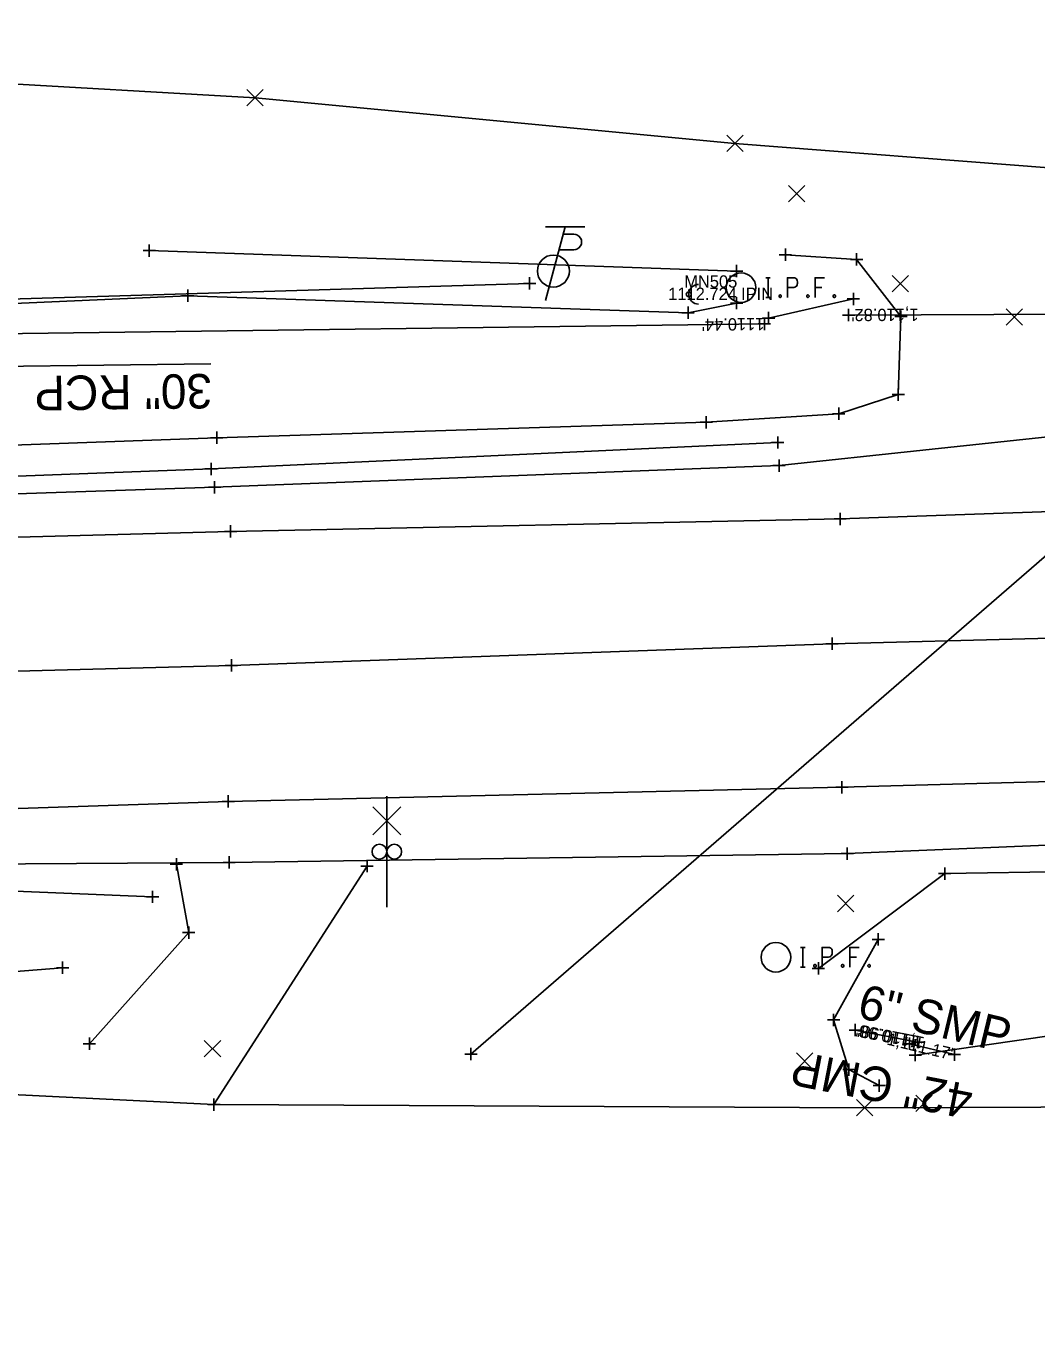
# Model space of a CAD drawing. Extents: x 2402028 to 2407435, y 498611 to 499105.
# Drawn here: x 2402973.4 to 2403055.5, y 498611.7 to 498717.9 of the extents above; entities that cross this region are included whole.
import ezdxf

# ---------------------------------------------------------------- set-up
doc = ezdxf.new("R2010")
doc.units = 0
for name, color, linetype in [('_CIVIL_CONSTRUCTION', 7, 'Continuous'), ('Default', 7, 'Continuous'), ('DR_X_Ditch', 7, 'Continuous'), ('DR_X_Storm_Sewer', 7, 'Continuous'), ('DR_X_Text', 7, 'Continuous'), ('PV_X_COP', 7, 'Continuous'), ('PV_X_Driveway', 7, 'Continuous'), ('PV_X_EOP', 7, 'Continuous'), ('PV_X_Shoulder', 7, 'Continuous'), ('RD_X_GR_Lt', 7, 'Continuous'), ('RD_X_RR_1', 7, 'Continuous'), ('RW_X_CL_100_Bearings', 7, 'Continuous'), ('RW_X_CL_100_Cardinal_Points', 7, 'Continuous'), ('RW_X_CL_100_Stations', 7, 'Continuous'), ('RW_X_CL_500_Bearings', 7, 'Continuous'), ('RW_X_CL_500_Cardinal_Points', 7, 'Continuous'), ('RW_X_CL_500_Distances', 7, 'Continuous'), ('RW_X_CL_500_Stations', 7, 'Continuous'), ('RW_X_Esmt_RR', 7, 'Continuous'), ('SC_Scratch1', 7, 'Continuous'), ('SV_X_Break_Lines', 7, 'Continuous'), ('SV_X_Terrain_Boundary', 7, 'Continuous'), ('UT_X_Telecom', 7, 'Continuous')]:
    doc.layers.add(name, color=color, linetype=linetype)

msp = doc.modelspace()

# ---------------------------------------------------------------- linework, layer by layer
at = {"layer": 'Default'}
for p, q in [((2403045.13, 498635.18), (2403045.13, 498635.18)), ((2403045.78, 498635.32), (2403045.78, 498635.32))]:
    msp.add_line(p, q, dxfattribs=at)
at = {"layer": 'DR_X_Ditch'}
msp.add_lwpolyline([(2403033.68, 498694.14), (2403040.56, 498695.7)], dxfattribs=at)
at = {"layer": 'DR_X_Storm_Sewer'}
for p, q in [((2403115.62, 498694.73), (2403040.17, 498694.38)), ((2403033.33, 498693.66), (2402928.26, 498692.31)), ((2403045.78, 498635.32), (2403040.71, 498636.3)), ((2403045.13, 498635.18), (2403048.77, 498634.3))]:
    msp.add_line(p, q, dxfattribs=at)
at = {"layer": 'DR_X_Text'}
msp.add_line((2402969.29, 498690.19), (2402988.37, 498690.43), dxfattribs=at)
at = {"layer": 'PV_X_COP'}
msp.add_lwpolyline([(2402290.78, 498650.6), (2402340.95, 498651.54), (2402390.57, 498652.34), (2402439.7, 498652.49), (2402489.93, 498654.64), (2402539.81, 498655.53), (2402589.95, 498657.15), (2402640.38, 498659.77), (2402689.17, 498658.83), (2402739.11, 498659.65), (2402789.43, 498660.95), (2402839.82, 498661.75), (2402889.36, 498663.57), (2402939.81, 498664.58), (2402990.03, 498665.92), (2403038.83, 498667.68), (2403088.96, 498668.97), (2403139.3, 498669.99), (2403188.98, 498670.93), (2403236.78, 498672.43), (2403288.95, 498673.92), (2403339.4, 498675.07), (2403388.6, 498676.54)], dxfattribs=at)
at = {"layer": 'PV_X_Driveway'}
for points in [[(2402978.5, 498635.18), (2402986.56, 498644.22), (2402985.56, 498649.77)], [(2403001.06, 498649.62), (2402988.61, 498630.24)]]:
    msp.add_lwpolyline(points, dxfattribs=at)
at = {"layer": 'PV_X_EOP'}
for points in [[(2402289.63, 498661.52), (2402339.86, 498662.34), (2402390.35, 498663.57), (2402439.38, 498664.47), (2402489.03, 498665.67), (2402538.63, 498666.7), (2402622.2, 498668.45), (2402639.44, 498668.97), (2402688.21, 498669.91), (2402738.3, 498670.77), (2402784.26, 498671.54), (2402839.07, 498673.4), (2402887.81, 498674.54), (2402939.07, 498675.44), (2402989.96, 498676.81), (2403039.49, 498677.82), (2403088.59, 498679.54), (2403138.58, 498681), (2403188.48, 498682.36), (2403236.31, 498683.8), (2403287.8, 498685.14), (2403338.61, 498686.54), (2403387.34, 498688.53)], [(2402290.91, 498639.29), (2402341.07, 498640.3), (2402390.61, 498641.23), (2402440.65, 498642.38), (2402490.15, 498643.23), (2402540.35, 498644.45), (2402590.8, 498645.77), (2402640.33, 498646.73), (2402690.18, 498647.64), (2402739.92, 498648.63), (2402790, 498649.56), (2402840.05, 498650.65), (2402889.89, 498651.78), (2402940.17, 498653.2), (2402989.78, 498654.87), (2403039.63, 498656.02), (2403089.54, 498657.39), (2403140.04, 498658.56), (2403189.82, 498659.81), (2403238.57, 498661.04), (2403289.76, 498662.62), (2403340.13, 498663.91), (2403389.07, 498665.43)]]:
    msp.add_lwpolyline(points, dxfattribs=at)
at = {"layer": 'PV_X_Shoulder'}
for p, q in [((2403034.53, 498682.16), (2403062.85, 498685.18)), ((2402988.67, 498680.4), (2403034.53, 498682.16)), ((2402938.19, 498678.69), (2402988.67, 498680.4))]:
    msp.add_line(p, q, dxfattribs=at)
msp.add_lwpolyline([(2402291.13, 498635.58), (2402341.06, 498636.96), (2402390.62, 498637.69), (2402440.73, 498638.55), (2402490.3, 498639.85), (2402540.78, 498641.01), (2402590.73, 498641.96), (2402640.23, 498642.72), (2402690.38, 498643.95), (2402740.06, 498644.93), (2402790, 498645.7), (2402840.23, 498646.8), (2402889.99, 498648.42), (2402940.22, 498649.59), (2402989.85, 498649.92), (2403040.06, 498650.63), (2403089.93, 498652.73), (2403140.24, 498654.26), (2403189.57, 498655.62), (2403238.67, 498657.76), (2403289.89, 498659.04), (2403340.12, 498659.5), (2403389.1, 498660.69)], dxfattribs=at)
at = {"layer": 'RD_X_GR_Lt'}
for points in [[(2402671.34, 498674.03), (2402687.6, 498674.22), (2402737.25, 498674.66), (2402787.14, 498675.21), (2402837.72, 498677.2), (2402886.73, 498678.51), (2402937.55, 498679.97), (2402988.38, 498681.88), (2403034.42, 498684.03)], [(2402983.63, 498647.12), (2402940.38, 498648.9), (2402890.36, 498647.43), (2402840.29, 498646.11), (2402790.18, 498644.6), (2402758.45, 498643.74)]]:
    msp.add_lwpolyline(points, dxfattribs=at)
at = {"layer": 'RD_X_RR_1'}
msp.add_lwpolyline([(2403009.49, 498634.34), (2403091.64, 498705.57)], dxfattribs=at)
at = {"layer": 'RW_X_CL_100_Stations'}
for points in [[(2403033.46, 498697.41), (2403033.81, 498697.41)], [(2403033.63, 498695.81), (2403033.63, 498697.41)], [(2403035.2, 498695.81), (2403035.2, 498697.41), (2403035.73, 498697.41), (2403035.78, 498697.4), (2403035.86, 498697.37), (2403035.89, 498697.35), (2403035.93, 498697.32), (2403035.97, 498697.26), (2403036, 498697.2), (2403036.03, 498697.09), (2403036.03, 498696.94), (2403036.01, 498696.89), (2403035.99, 498696.82), (2403035.95, 498696.73), (2403035.9, 498696.69), (2403035.87, 498696.67), (2403035.82, 498696.64), (2403035.73, 498696.63), (2403035.2, 498696.63)], [(2403038.21, 498697.41), (2403037.45, 498697.41), (2403037.45, 498695.81)], [(2403037.45, 498696.63), (2403037.99, 498696.63)], [(2403033.46, 498695.81), (2403033.81, 498695.81)], [(2403034.59, 498696.02), (2403034.65, 498696.02), (2403034.68, 498696), (2403034.71, 498695.95), (2403034.71, 498695.89), (2403034.68, 498695.83), (2403034.65, 498695.81), (2403034.59, 498695.81), (2403034.56, 498695.83), (2403034.53, 498695.89), (2403034.53, 498695.95), (2403034.56, 498696), (2403034.59, 498696.02)], [(2403036.84, 498696.02), (2403036.9, 498696.02), (2403036.93, 498696), (2403036.96, 498695.95), (2403036.96, 498695.89), (2403036.93, 498695.83), (2403036.9, 498695.81), (2403036.84, 498695.81), (2403036.81, 498695.83), (2403036.77, 498695.89), (2403036.77, 498695.95), (2403036.81, 498696), (2403036.84, 498696.02)], [(2403038.99, 498696.02), (2403039.05, 498696.02), (2403039.08, 498696), (2403039.11, 498695.95), (2403039.11, 498695.89), (2403039.08, 498695.83), (2403039.05, 498695.81), (2403038.99, 498695.81), (2403038.96, 498695.83), (2403038.92, 498695.89), (2403038.92, 498695.95), (2403038.96, 498696), (2403038.99, 498696.02)], [(2403036.28, 498643.01), (2403036.64, 498643.01)], [(2403036.46, 498641.41), (2403036.46, 498643.01)], [(2403038.02, 498641.41), (2403038.02, 498643.01), (2403038.55, 498643.01), (2403038.61, 498643), (2403038.69, 498642.97), (2403038.72, 498642.95), (2403038.75, 498642.92), (2403038.8, 498642.86), (2403038.83, 498642.8), (2403038.85, 498642.7), (2403038.85, 498642.55), (2403038.84, 498642.5), (2403038.82, 498642.42), (2403038.77, 498642.33), (2403038.73, 498642.29), (2403038.7, 498642.27), (2403038.64, 498642.24), (2403038.55, 498642.23), (2403038.02, 498642.23)], [(2403041.03, 498643.01), (2403040.27, 498643.01), (2403040.27, 498641.41)], [(2403040.27, 498642.23), (2403040.81, 498642.23)], [(2403036.28, 498641.41), (2403036.64, 498641.41)], [(2403037.42, 498641.63), (2403037.47, 498641.63), (2403037.51, 498641.6), (2403037.54, 498641.55), (2403037.54, 498641.49), (2403037.51, 498641.44), (2403037.47, 498641.41), (2403037.42, 498641.41), (2403037.38, 498641.44), (2403037.35, 498641.49), (2403037.35, 498641.55), (2403037.38, 498641.6), (2403037.42, 498641.63)], [(2403039.67, 498641.63), (2403039.72, 498641.63), (2403039.75, 498641.6), (2403039.79, 498641.55), (2403039.79, 498641.49), (2403039.75, 498641.44), (2403039.72, 498641.41), (2403039.67, 498641.41), (2403039.63, 498641.44), (2403039.6, 498641.49), (2403039.6, 498641.55), (2403039.63, 498641.6), (2403039.67, 498641.63)], [(2403041.82, 498641.63), (2403041.87, 498641.63), (2403041.9, 498641.6), (2403041.94, 498641.55), (2403041.94, 498641.49), (2403041.9, 498641.44), (2403041.87, 498641.41), (2403041.82, 498641.41), (2403041.78, 498641.44), (2403041.75, 498641.49), (2403041.75, 498641.55), (2403041.78, 498641.6), (2403041.82, 498641.63)]]:
    msp.add_lwpolyline(points, dxfattribs=at)
for centre in [(2403031.44, 498696.61), (2403034.27, 498642.21)]:
    msp.add_circle(centre, 1.2, dxfattribs=at)
at = {"layer": 'RW_X_CL_500_Bearings'}
for p, q in [((2402982.86, 498699.62), (2402983.86, 498699.62)), ((2402983.36, 498700.12), (2402983.36, 498699.12)), ((2402983.36, 498699.62), (2402983.36, 498699.62)), ((2403035.04, 498699.78), (2403035.04, 498698.78)), ((2403031.07, 498698.45), (2403031.07, 498697.45)), ((2403034.54, 498699.28), (2403035.54, 498699.28)), ((2403035.04, 498699.28), (2403035.04, 498699.28)), ((2403040.33, 498698.9), (2403041.33, 498698.9)), ((2403040.83, 498699.4), (2403040.83, 498698.4)), ((2403040.83, 498698.9), (2403040.83, 498698.9)), ((2403014.26, 498697.45), (2403014.26, 498696.45)), ((2403030.57, 498697.95), (2403031.57, 498697.95)), ((2403031.07, 498697.95), (2403031.07, 498697.95)), ((2402986.48, 498696.45), (2402986.48, 498695.45)), ((2403013.76, 498696.95), (2403014.76, 498696.95)), ((2403014.26, 498696.95), (2403014.26, 498696.95)), ((2402985.98, 498695.95), (2402986.98, 498695.95)), ((2402986.48, 498695.95), (2402986.48, 498695.95)), ((2403030.57, 498695.35), (2403031.57, 498695.35)), ((2403031.07, 498695.85), (2403031.07, 498694.85)), ((2403031.07, 498695.35), (2403031.07, 498695.35)), ((2403040.06, 498695.7), (2403041.06, 498695.7)), ((2403040.56, 498696.2), (2403040.56, 498695.2)), ((2403040.56, 498695.7), (2403040.56, 498695.7)), ((2403026.63, 498694.57), (2403027.63, 498694.57)), ((2403027.13, 498695.07), (2403027.13, 498694.07)), ((2403027.13, 498694.57), (2403027.13, 498694.57)), ((2403033.68, 498694.64), (2403033.68, 498693.64)), ((2403043.92, 498694.26), (2403044.92, 498694.26)), ((2403044.42, 498694.76), (2403044.42, 498693.76)), ((2403044.42, 498694.26), (2403044.42, 498694.26)), ((2403033.18, 498694.14), (2403034.18, 498694.14)), ((2403033.68, 498694.14), (2403033.68, 498694.14)), ((2403043.71, 498687.92), (2403044.71, 498687.92)), ((2403044.21, 498688.42), (2403044.21, 498687.42)), ((2403044.21, 498687.92), (2403044.21, 498687.92)), ((2403039.38, 498686.87), (2403039.38, 498685.87)), ((2403028.61, 498686.17), (2403028.61, 498685.17)), ((2403038.88, 498686.37), (2403039.88, 498686.37)), ((2403039.38, 498686.37), (2403039.38, 498686.37)), ((2402988.84, 498684.91), (2402988.84, 498683.91)), ((2403028.11, 498685.67), (2403029.11, 498685.67)), ((2403028.61, 498685.67), (2403028.61, 498685.67)), ((2402988.34, 498684.41), (2402989.34, 498684.41)), ((2402988.84, 498684.41), (2402988.84, 498684.41)), ((2403033.92, 498684.03), (2403034.92, 498684.03)), ((2403034.42, 498684.53), (2403034.42, 498683.53)), ((2403034.42, 498684.03), (2403034.42, 498684.03)), ((2403034.53, 498682.66), (2403034.53, 498681.66)), ((2402987.88, 498681.88), (2402988.88, 498681.88)), ((2402988.38, 498682.38), (2402988.38, 498681.38)), ((2402988.38, 498681.88), (2402988.38, 498681.88)), ((2403034.03, 498682.16), (2403035.03, 498682.16)), ((2403034.53, 498682.16), (2403034.53, 498682.16)), ((2402988.17, 498680.4), (2402989.17, 498680.4)), ((2402988.67, 498680.9), (2402988.67, 498679.9)), ((2402988.67, 498680.4), (2402988.67, 498680.4)), ((2403039.49, 498678.32), (2403039.49, 498677.32)), ((2402989.96, 498677.31), (2402989.96, 498676.31)), ((2403038.99, 498677.82), (2403039.99, 498677.82)), ((2403039.49, 498677.82), (2403039.49, 498677.82)), ((2402989.46, 498676.81), (2402990.46, 498676.81)), ((2402989.96, 498676.81), (2402989.96, 498676.81)), ((2403038.33, 498667.68), (2403039.33, 498667.68)), ((2403038.83, 498668.18), (2403038.83, 498667.18)), ((2403038.83, 498667.68), (2403038.83, 498667.68)), ((2402989.53, 498665.92), (2402990.53, 498665.92)), ((2402990.03, 498666.42), (2402990.03, 498665.42)), ((2402990.03, 498665.92), (2402990.03, 498665.92)), ((2403039.13, 498656.02), (2403040.13, 498656.02)), ((2403039.63, 498656.52), (2403039.63, 498655.52)), ((2403039.63, 498656.02), (2403039.63, 498656.02)), ((2402989.78, 498655.37), (2402989.78, 498654.37)), ((2402989.28, 498654.87), (2402990.28, 498654.87)), ((2402989.78, 498654.87), (2402989.78, 498654.87)), ((2403040.06, 498651.13), (2403040.06, 498650.13)), ((2402985.06, 498649.77), (2402986.06, 498649.77)), ((2402985.56, 498650.27), (2402985.56, 498649.27)), ((2402985.56, 498649.77), (2402985.56, 498649.77)), ((2402989.35, 498649.92), (2402990.35, 498649.92)), ((2402989.85, 498650.42), (2402989.85, 498649.42)), ((2402989.85, 498649.92), (2402989.85, 498649.92)), ((2403000.56, 498649.62), (2403001.56, 498649.62)), ((2403001.06, 498650.12), (2403001.06, 498649.12)), ((2403001.06, 498649.62), (2403001.06, 498649.62)), ((2403039.56, 498650.63), (2403040.56, 498650.63)), ((2403040.06, 498650.63), (2403040.06, 498650.63)), ((2403047.49, 498649.01), (2403048.49, 498649.01)), ((2403047.99, 498649.51), (2403047.99, 498648.51)), ((2403047.99, 498649.01), (2403047.99, 498649.01)), ((2402983.63, 498647.62), (2402983.63, 498646.62)), ((2402983.13, 498647.12), (2402984.13, 498647.12)), ((2402983.63, 498647.12), (2402983.63, 498647.12)), ((2402986.56, 498644.72), (2402986.56, 498643.72)), ((2402986.06, 498644.22), (2402987.06, 498644.22)), ((2402986.56, 498644.22), (2402986.56, 498644.22)), ((2403042.08, 498643.66), (2403043.08, 498643.66)), ((2403042.58, 498644.16), (2403042.58, 498643.16)), ((2403042.58, 498643.66), (2403042.58, 498643.66)), ((2402975.82, 498641.36), (2402976.82, 498641.36)), ((2402976.32, 498641.86), (2402976.32, 498640.86)), ((2402976.32, 498641.36), (2402976.32, 498641.36)), ((2403037.22, 498641.31), (2403038.22, 498641.31)), ((2403037.72, 498641.81), (2403037.72, 498640.81)), ((2403037.72, 498641.31), (2403037.72, 498641.31)), ((2403038.45, 498637.12), (2403039.45, 498637.12)), ((2403038.95, 498637.62), (2403038.95, 498636.62)), ((2403038.95, 498637.12), (2403038.95, 498637.12)), ((2402978, 498635.18), (2402979, 498635.18)), ((2402978.5, 498635.68), (2402978.5, 498634.68)), ((2402978.5, 498635.18), (2402978.5, 498635.18)), ((2403009.49, 498634.84), (2403009.49, 498633.84)), ((2403045.59, 498634.76), (2403045.59, 498633.76)), ((2403008.99, 498634.34), (2403009.99, 498634.34)), ((2403009.49, 498634.34), (2403009.49, 498634.34)), ((2403045.09, 498634.26), (2403046.09, 498634.26)), ((2403045.59, 498634.26), (2403045.59, 498634.26)), ((2403039.7, 498633.09), (2403040.7, 498633.09)), ((2403040.2, 498633.59), (2403040.2, 498632.59)), ((2403040.2, 498633.09), (2403040.2, 498633.09)), ((2403042.17, 498631.79), (2403043.17, 498631.79)), ((2403042.67, 498632.29), (2403042.67, 498631.29)), ((2403042.67, 498631.79), (2403042.67, 498631.79)), ((2402988.61, 498630.74), (2402988.61, 498629.74)), ((2402988.11, 498630.24), (2402989.11, 498630.24)), ((2402988.61, 498630.24), (2402988.61, 498630.24))]:
    msp.add_line(p, q, dxfattribs=at)
at = {"layer": 'RW_X_CL_500_Cardinal_Points'}
for p, q in [((2403017.15, 498701.56), (2403015.54, 498695.56)), ((2403018.75, 498701.56), (2403015.55, 498701.56)), ((2403016.99, 498700.96), (2403017.84, 498700.96)), ((2403016.65, 498699.68), (2403017.84, 498699.68))]:
    msp.add_line(p, q, dxfattribs=at)
for centre, radius in [((2403016.19, 498697.96), 1.3), ((2403027.19, 498696.07), 0.2)]:
    msp.add_circle(centre, radius, dxfattribs=at)
for centre, radius, start, end in [((2403017.85, 498700.32), 0.638, 268.8767, 91.1233), ((2403027.99, 498696.07), 0.8, 90, 270)]:
    msp.add_arc(centre, radius, start, end, dxfattribs=at)
at = {"layer": 'RW_X_CL_500_Distances'}
for p, q in [((2403039.67, 498694.38), (2403040.67, 498694.38)), ((2403040.17, 498694.88), (2403040.17, 498693.88)), ((2403040.17, 498694.38), (2403040.17, 498694.38)), ((2403032.83, 498693.66), (2403033.83, 498693.66)), ((2403033.33, 498694.16), (2403033.33, 498693.16)), ((2403033.33, 498693.66), (2403033.33, 498693.66)), ((2403040.21, 498636.3), (2403041.21, 498636.3)), ((2403040.71, 498636.8), (2403040.71, 498635.8)), ((2403040.71, 498636.3), (2403040.71, 498636.3)), ((2403045.78, 498635.82), (2403045.78, 498634.82)), ((2403044.63, 498635.18), (2403045.63, 498635.18)), ((2403045.13, 498635.68), (2403045.13, 498634.68)), ((2403045.13, 498635.18), (2403045.13, 498635.18)), ((2403045.28, 498635.32), (2403046.28, 498635.32)), ((2403045.78, 498635.32), (2403045.78, 498635.32)), ((2403048.77, 498634.8), (2403048.77, 498633.8)), ((2403048.27, 498634.3), (2403049.27, 498634.3)), ((2403048.77, 498634.3), (2403048.77, 498634.3))]:
    msp.add_line(p, q, dxfattribs=at)
at = {"layer": 'RW_X_CL_500_Stations'}
for p, q in [((2402991.29, 498711.37), (2402992.62, 498712.71)), ((2402991.29, 498712.71), (2402992.62, 498711.37)), ((2403030.27, 498707.67), (2403031.61, 498709)), ((2403030.27, 498709), (2403031.61, 498707.67)), ((2403035.29, 498703.57), (2403036.62, 498704.9)), ((2403035.29, 498704.9), (2403036.62, 498703.57)), ((2403043.71, 498696.26), (2403045.04, 498697.6)), ((2403043.71, 498697.6), (2403045.04, 498696.26)), ((2403052.98, 498693.55), (2403054.31, 498694.89)), ((2403052.98, 498694.89), (2403054.31, 498693.55)), ((2403039.28, 498645.91), (2403040.61, 498647.25)), ((2403039.28, 498647.25), (2403040.61, 498645.91)), ((2402987.83, 498634.12), (2402989.17, 498635.46)), ((2402987.83, 498635.46), (2402989.17, 498634.12)), ((2403035.94, 498633.1), (2403037.27, 498634.44)), ((2403035.94, 498634.44), (2403037.27, 498633.1)), ((2403040.81, 498629.32), (2403042.14, 498630.65)), ((2403040.81, 498630.65), (2403042.14, 498629.32)), ((2403045.64, 498629.69), (2403046.97, 498631.02)), ((2403045.64, 498631.02), (2403046.97, 498629.69))]:
    msp.add_line(p, q, dxfattribs=at)
at = {"layer": 'RW_X_Esmt_RR'}
for p, q in [((2403002.66, 498646.29), (2403002.66, 498655.29)), ((2403003.8, 498652.16), (2403001.53, 498654.42)), ((2403001.53, 498652.16), (2403003.8, 498654.42))]:
    msp.add_line(p, q, dxfattribs=at)
for centre in [(2403002.06, 498650.79), (2403003.26, 498650.79)]:
    msp.add_circle(centre, 0.6, dxfattribs=at)
at = {"layer": 'SV_X_Break_Lines'}
for points in [[(2403031.07, 498697.95), (2402983.36, 498699.62)], [(2402288.25, 498667.48), (2402339.69, 498668.17), (2402389.86, 498669.48), (2402438.42, 498670.54), (2402588.11, 498673.81), (2402638.99, 498674.42), (2402672.44, 498676.2), (2402688.28, 498675.46), (2402738.27, 498675.88), (2402788.35, 498678.35), (2402793.91, 498678.03), (2402796.15, 498678.69), (2402799.15, 498678), (2402838.74, 498678.94), (2402887.97, 498680.68), (2402923.89, 498681.63), (2402938.31, 498682.59), (2402988.84, 498684.41), (2403028.61, 498685.67), (2403039.38, 498686.37), (2403044.21, 498687.92), (2403044.42, 498694.26), (2403040.83, 498698.9), (2403035.04, 498699.28)], [(2402931.65, 498689.7), (2402941.65, 498693.97), (2402986.48, 498695.95), (2403027.13, 498694.57), (2403031.07, 498695.35)], [(2403326.04, 498656.48), (2403290.07, 498656.88), (2403238.78, 498655.67), (2403189.96, 498653.45), (2403140.22, 498651.66), (2403089.48, 498649.66), (2403047.99, 498649.01), (2403037.72, 498641.31)], [(2403325.44, 498652.67), (2403290.46, 498651.22), (2403239.36, 498647.62), (2403189.92, 498644.45), (2403141.13, 498642.82), (2403090.47, 498640.74), (2403045.59, 498634.26)], [(2403042.58, 498643.66), (2403038.95, 498637.12), (2403040.2, 498633.09), (2403042.67, 498631.79)], [(2402976.32, 498641.36), (2402940.23, 498638.5), (2402890.46, 498637.38), (2402840.04, 498637.93), (2402803.61, 498636.34), (2402801.54, 498636.51), (2402797.21, 498636.06), (2402793.66, 498636.1), (2402790.59, 498637.18), (2402761.78, 498637.43)]]:
    msp.add_lwpolyline(points, dxfattribs=at)
at = {"layer": 'SV_X_Terrain_Boundary'}
for points in [[(2403390.54, 498717.85), (2403340.67, 498716.01), (2403291.04, 498712.96), (2403238.44, 498711.46), (2403188.93, 498712.35), (2403141.78, 498709.87), (2403108.52, 498702.31), (2403030.94, 498708.33), (2402991.96, 498712.04), (2402946.72, 498714.63), (2402886.9, 498701.35), (2402808.26, 498712.11), (2402805.63, 498711.55), (2402802.55, 498713.98), (2402800.83, 498712.58), (2402791.73, 498715.48), (2402739.88, 498694.44), (2402686.71, 498702.37), (2402636.92, 498697.87)], [(2402641.3, 498620.88), (2402692.24, 498622.71), (2402740.26, 498624.67), (2402793.66, 498636.1), (2402843.48, 498611.7), (2402939.98, 498632.65), (2402988.61, 498630.24), (2403041.47, 498629.99), (2403091.65, 498630.18), (2403191.21, 498636.27), (2403240.26, 498637.09), (2403290.41, 498638.6), (2403346.11, 498636.26), (2403438.36, 498646.02)]]:
    msp.add_lwpolyline(points, dxfattribs=at)
at = {"layer": 'UT_X_Telecom'}
msp.add_lwpolyline([(2402854.08, 498692.14), (2403014.26, 498696.95)], dxfattribs=at)

# ---------------------------------------------------------------- texts
at = {"layer": '_CIVIL_CONSTRUCTION'}
msp.add_text('MN505', height=1, dxfattribs=at).set_placement((2403026.82, 498696.61))
at = {"layer": 'DR_X_Text'}
for s, rotation, p in [('30" RCP', 180.7345, (2402988.44, 498689.61)), ('6" SMP', 346.4424, (2403040.77, 498637.34)), ('42" CMP', 169.0031, (2403050.43, 498631.79))]:
    msp.add_text(s, height=2.8, rotation=rotation, dxfattribs=at).set_placement(p)
at = {"layer": 'RW_X_CL_100_Bearings'}
msp.add_text('1112.724', height=1, dxfattribs=at).set_placement((2403025.52, 498695.61))
at = {"layer": 'RW_X_CL_100_Cardinal_Points'}
msp.add_text('IPIN', height=1, dxfattribs=at).set_placement((2403031.44, 498695.61))
at = {"layer": 'SC_Scratch1'}
for s, rotation, p in [("1,110.82'", 180.2665, (2403045.86, 498694.91)), ("1110.44'", 180.7345, (2403033.33, 498694.16)), ("1110.98'", 169.0031, (2403045.88, 498635.81)), ("1,110.98'", 169.0031, (2403046.39, 498635.71)), ("1,111.17'", 346.4424, (2403043.22, 498635.13))]:
    msp.add_text(s, height=1, rotation=rotation, dxfattribs=at).set_placement(p)

doc.saveas('drawing.dxf')
